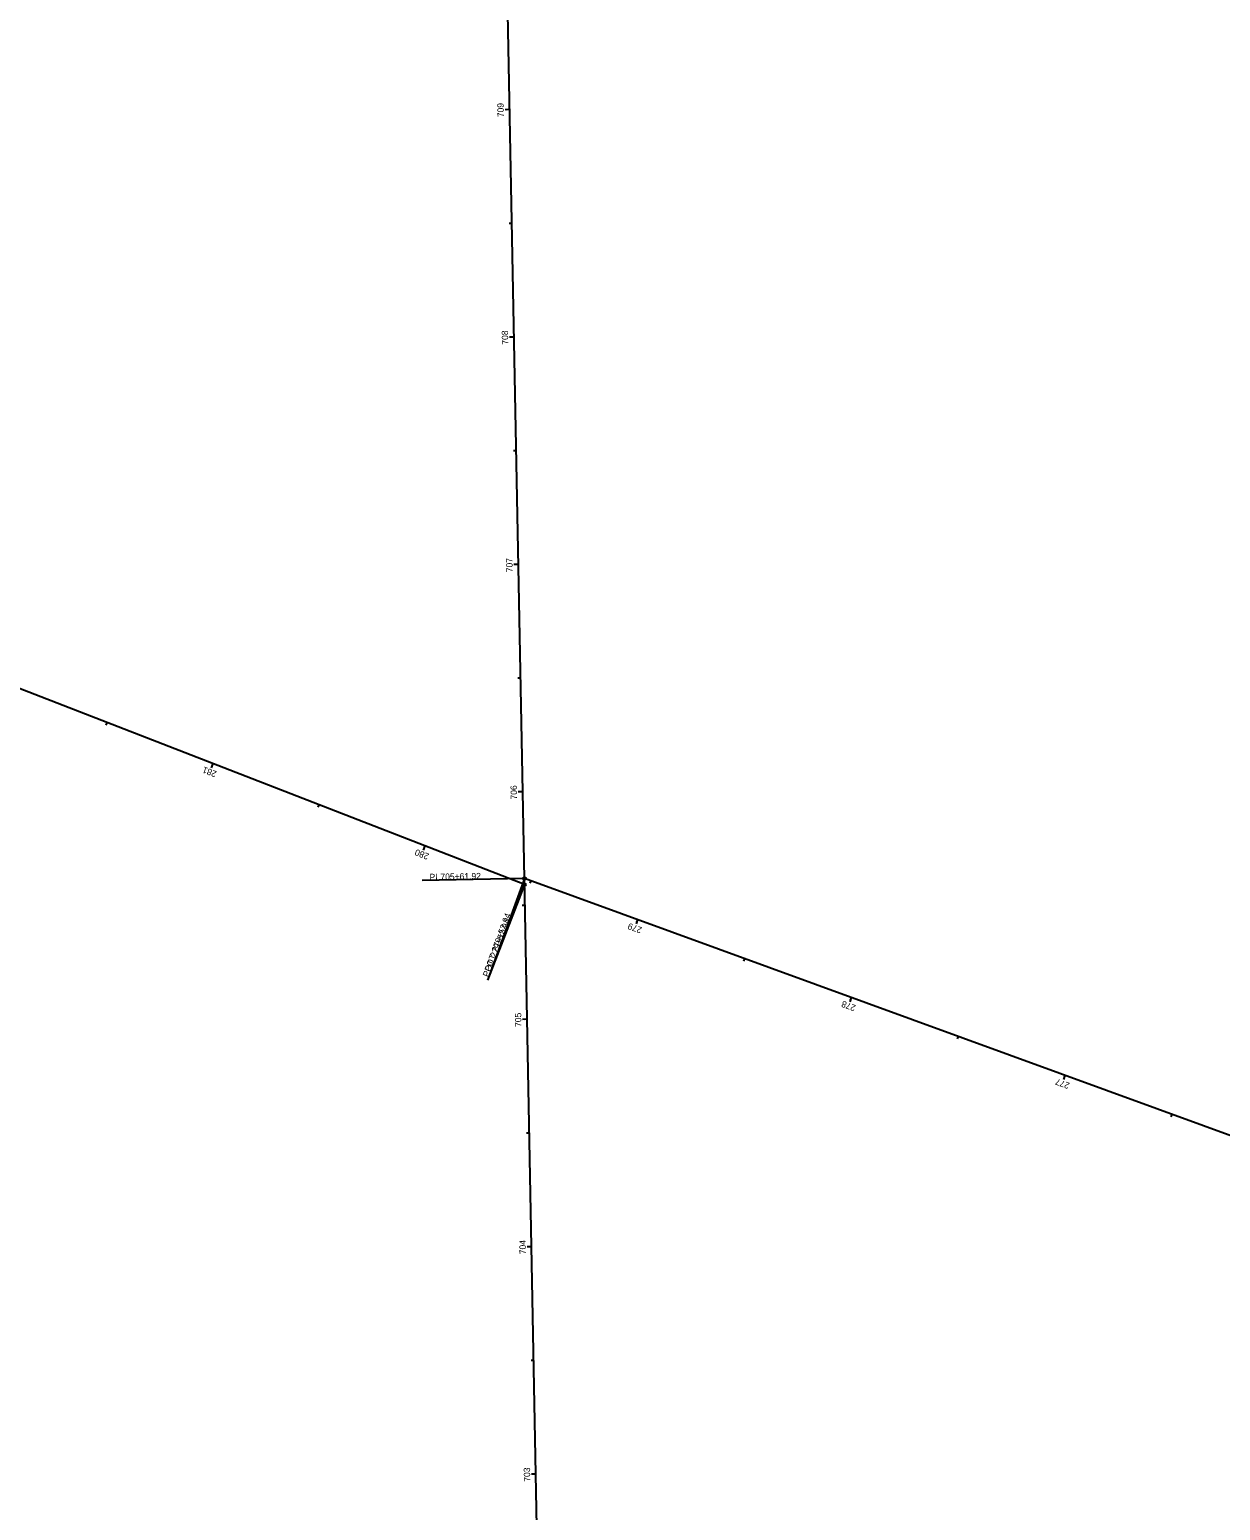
# Model space of a CAD drawing. Extents: x 2045805 to 2050091, y 455249 to 458900.
# Drawn here: x 2047414 to 2047937, y 456718 to 457369 of the extents above; entities that cross this region are included whole.
import ezdxf

# ---------------------------------------------------------------- set-up
doc = ezdxf.new("R2010")
doc.units = 0
for name, color, linetype in [('GE_P_Alignment_100_Bearings', 7, 'Continuous'), ('GE_P_Alignment_100_Cardinal_Points', 7, 'Continuous'), ('GE_P_Alignment_100_Distances', 7, 'Continuous'), ('GE_P_Alignment_100_Stations', 7, 'Continuous'), ('PF_P_Grade_Line', 7, 'Continuous'), ('PV_P_EOP', 7, 'Continuous'), ('PV_X_EOP', 7, 'Continuous')]:
    doc.layers.add(name, color=color, linetype=linetype)

msp = doc.modelspace()

# ---------------------------------------------------------------- linework, layer by layer
at = {"layer": 'GE_P_Alignment_100_Bearings'}
for p, q in [((2047631.15, 456996.2), (2047586.16, 456995.33)), ((2047631.15, 456996.2), (2047615.76, 456953.91)), ((2047631.2, 456993.49), (2047614.92, 456951.54))]:
    msp.add_line(p, q, dxfattribs=at)
for centre in [(2047631.15, 456996.2), (2047631.15, 456996.2), (2047631.2, 456993.49)]:
    msp.add_circle(centre, 0.6, dxfattribs=at)
at = {"layer": 'GE_P_Alignment_100_Cardinal_Points'}
for p, q in [((2047624.61, 457334.22), (2047622.61, 457334.18)), ((2047625.58, 457284.23), (2047624.38, 457284.2)), ((2047626.54, 457234.24), (2047624.54, 457234.2)), ((2047627.51, 457184.25), (2047626.31, 457184.22)), ((2047628.48, 457134.26), (2047626.48, 457134.22)), ((2047629.45, 457084.27), (2047628.25, 457084.24)), ((2047447.49, 457064.78), (2047447.06, 457063.66)), ((2047494.1, 457046.69), (2047493.38, 457044.83)), ((2047540.72, 457028.6), (2047540.28, 457027.49)), ((2047630.41, 457034.27), (2047628.42, 457034.24)), ((2047587.33, 457010.51), (2047586.61, 457008.65)), ((2047633.91, 456995.19), (2047633.5, 456994.07)), ((2047631.38, 456984.28), (2047630.18, 456984.26)), ((2047680.9, 456978.1), (2047680.22, 456976.22)), ((2047727.89, 456961), (2047727.48, 456959.87)), ((2047774.87, 456943.9), (2047774.19, 456942.02)), ((2047632.35, 456934.29), (2047630.35, 456934.25)), ((2047821.86, 456926.8), (2047821.45, 456925.68)), ((2047868.84, 456909.71), (2047868.16, 456907.83)), ((2047915.83, 456892.61), (2047915.42, 456891.48)), ((2047633.32, 456884.3), (2047632.12, 456884.28)), ((2047634.29, 456834.31), (2047632.29, 456834.27)), ((2047635.25, 456784.32), (2047634.05, 456784.3)), ((2047636.22, 456734.33), (2047634.22, 456734.29))]:
    msp.add_line(p, q, dxfattribs=at)
at = {"layer": 'GE_P_Alignment_100_Distances'}
for p, q in [((2047631.15, 456996.2), (2047586.16, 456995.33)), ((2047631.15, 456996.2), (2047615.76, 456953.91)), ((2047631.2, 456993.49), (2047614.92, 456951.54))]:
    msp.add_line(p, q, dxfattribs=at)
for centre in [(2047631.15, 456996.2), (2047631.15, 456996.2), (2047631.2, 456993.49)]:
    msp.add_circle(centre, 0.6, dxfattribs=at)
at = {"layer": 'GE_P_Alignment_100_Stations'}
for p, q in [((2047624.61, 457334.22), (2047623.41, 457334.2)), ((2047626.54, 457234.24), (2047625.34, 457234.21)), ((2047628.48, 457134.26), (2047627.28, 457134.23)), ((2047494.1, 457046.69), (2047493.67, 457045.57)), ((2047630.41, 457034.27), (2047629.22, 457034.25)), ((2047587.33, 457010.51), (2047586.61, 457008.65)), ((2047680.9, 456978.1), (2047680.49, 456976.97)), ((2047774.87, 456943.9), (2047774.46, 456942.77)), ((2047632.35, 456934.29), (2047630.35, 456934.25)), ((2047868.84, 456909.71), (2047868.43, 456908.58)), ((2047634.29, 456834.31), (2047633.09, 456834.29)), ((2047636.22, 456734.33), (2047635.02, 456734.31))]:
    msp.add_line(p, q, dxfattribs=at)
at = {"layer": 'PF_P_Grade_Line'}
for p, q in [((2047631.15, 456996.2), (2047586.16, 456995.33)), ((2047631.15, 456996.2), (2047615.76, 456953.91)), ((2047631.2, 456993.49), (2047614.92, 456951.54))]:
    msp.add_line(p, q, dxfattribs=at)
for centre in [(2047631.15, 456996.2), (2047631.15, 456996.2), (2047631.2, 456993.49)]:
    msp.add_circle(centre, 0.6, dxfattribs=at)
at = {"layer": 'PV_P_EOP'}
for p, q in [((2047631.15, 456996.2), (2047613.37, 457914.72)), ((2047631.2, 456993.49), (2046922.17, 457268.65)), ((2047664.96, 455249.53), (2047631.15, 456996.2)), ((2050090.45, 456101.29), (2047631.15, 456996.2))]:
    msp.add_line(p, q, dxfattribs=at)
at = {"layer": 'PV_X_EOP'}
for p, q in [((2047587.33, 457010.51), (2047586.61, 457008.65)), ((2047632.35, 456934.29), (2047631.15, 456934.27))]:
    msp.add_line(p, q, dxfattribs=at)

# ---------------------------------------------------------------- texts
at = {"layer": 'GE_P_Alignment_100_Bearings'}
for s, rotation, p in [('PI', 1.10893, (2047589.46, 456995.44)), ('705+61.92', 1.10893, (2047594.24, 456995.53)), ('279+52.94', 68.78977, (2047618.6, 456961.15)), ('279+52.94', 70.00406, (2047619.24, 456963.6)), ('POT', 68.78977, (2047615.3, 456952.64)), ('POT', 70.00406, (2047616.12, 456955.02))]:
    msp.add_text(s, height=2.8, rotation=rotation, dxfattribs=at).set_placement(p)
at = {"layer": 'GE_P_Alignment_100_Cardinal_Points'}
for s, rotation, p in [('709', 91.10893, (2047622.13, 457330.92)), ('708', 91.10893, (2047624.06, 457230.91)), ('707', 91.10893, (2047626, 457130.87)), ('281', 158.78977, (2047496.08, 457043.19)), ('706', 91.10893, (2047627.93, 457030.94)), ('280', 158.78977, (2047589.47, 457006.95)), ('279', 160.00406, (2047683.09, 456974.59)), ('278', 160.00406, (2047777.08, 456940.39)), ('705', 91.10893, (2047629.87, 456930.95)), ('277', 160.00406, (2047871.13, 456906.21)), ('704', 91.10893, (2047631.8, 456831.02)), ('703', 91.10893, (2047633.74, 456731.02))]:
    msp.add_text(s, height=2.8, rotation=rotation, dxfattribs=at).set_placement(p)
at = {"layer": 'GE_P_Alignment_100_Distances'}
for s, rotation, p in [('PI', 1.10893, (2047589.46, 456995.44)), ('705+61.92', 1.10893, (2047594.24, 456995.53)), ('279+52.94', 68.78977, (2047618.6, 456961.15)), ('279+52.94', 70.00406, (2047619.24, 456963.6)), ('POT', 68.78977, (2047615.3, 456952.64)), ('POT', 70.00406, (2047616.12, 456955.02))]:
    msp.add_text(s, height=2.8, rotation=rotation, dxfattribs=at).set_placement(p)
at = {"layer": 'GE_P_Alignment_100_Stations'}
for s, rotation, p in [('280', 158.78977, (2047589.47, 457006.95)), ('705', 91.10893, (2047629.87, 456930.95))]:
    msp.add_text(s, height=2.8, rotation=rotation, dxfattribs=at).set_placement(p)
at = {"layer": 'PF_P_Grade_Line'}
for s, rotation, p in [('PI', 1.10893, (2047589.46, 456995.44)), ('705+61.92', 1.10893, (2047594.24, 456995.53)), ('279+52.94', 68.78977, (2047618.6, 456961.15)), ('279+52.94', 70.00406, (2047619.24, 456963.6)), ('POT', 68.78977, (2047615.3, 456952.64)), ('POT', 70.00406, (2047616.12, 456955.02))]:
    msp.add_text(s, height=2.8, rotation=rotation, dxfattribs=at).set_placement(p)
at = {"layer": 'PV_X_EOP'}
msp.add_text('280', height=2.8, rotation=158.78977, dxfattribs=at).set_placement((2047589.47, 457006.95))

doc.saveas('drawing.dxf')
